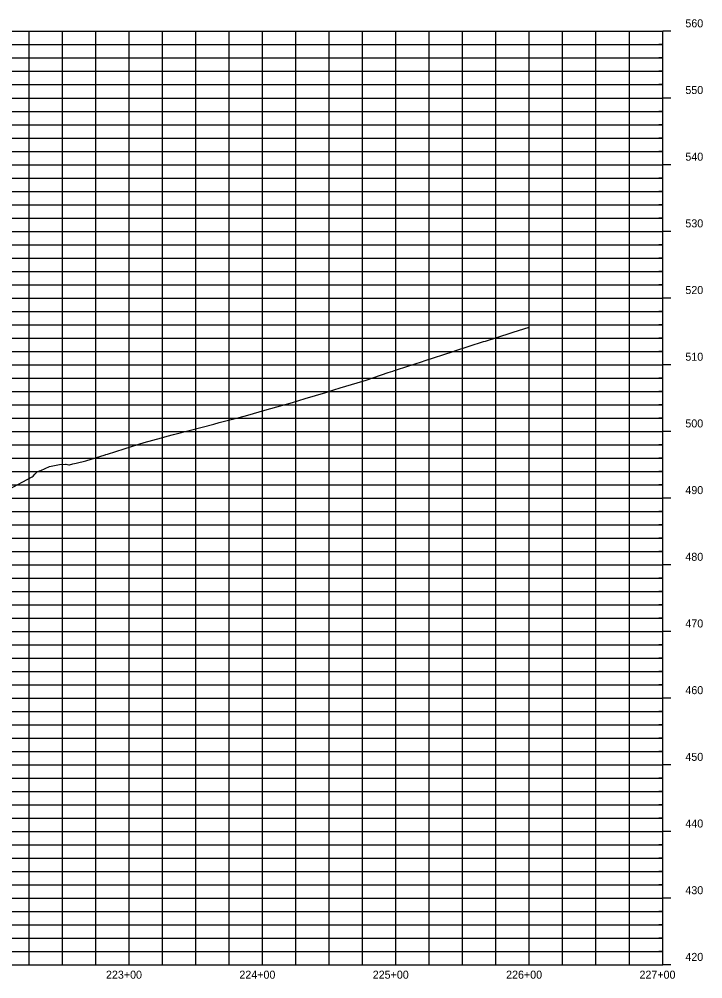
# Model space of a CAD drawing. Extents: x 1054002 to 1056762, y 395173 to 397393.
# Drawn here: x 1056250 to 1056762, y 395173 to 395893 of the extents above; entities that cross this region are included whole.
import ezdxf

# ---------------------------------------------------------------- set-up
doc = ezdxf.new("R2010")
doc.units = 0
for name, color, linetype in [('R_Axis_Annotation', 7, 'Continuous'), ('R_Exist Surface', 7, 'Continuous'), ('R_Grid', 7, 'Continuous'), ('R_Grid Annot', 7, 'Continuous'), ('R_Grid_Minor', 7, 'Continuous')]:
    doc.layers.add(name, color=color, linetype=linetype)

msp = doc.modelspace()

# ---------------------------------------------------------------- linework, layer by layer
at = {"layer": 'R_Exist Surface'}
msp.add_lwpolyline([(1056241.81, 395539.85), (1056259.67, 395549.45), (1056260.4, 395549.8), (1056261.45, 395551.26), (1056263.23, 395553.13), (1056263.71, 395553.34), (1056265.04, 395553.83), (1056265.14, 395553.88), (1056265.95, 395554.11), (1056272.48, 395557.17), (1056279.97, 395558.54), (1056284.63, 395558.84), (1056285.12, 395558.96), (1056287.08, 395558.26), (1056287.52, 395558.36), (1056289.96, 395559), (1056292.61, 395559.58), (1056299.79, 395561.45), (1056314.29, 395565.82), (1056314.9, 395565.99), (1056316.01, 395566.34), (1056334.83, 395572.32), (1056343.53, 395575.19), (1056356.5, 395578.61), (1056360.74, 395579.73), (1056365.53, 395581), (1056378.34, 395584.36), (1056395.66, 395588.9), (1056399.81, 395590.01), (1056414.66, 395593.91), (1056421.37, 395595.69), (1056433.9, 395599.33), (1056442.91, 395601.89), (1056454.64, 395605.21), (1056464.25, 395607.99), (1056479.62, 395612.64), (1056485.75, 395614.52), (1056490.43, 395615.97), (1056507.43, 395621.08), (1056509.94, 395621.93), (1056526.58, 395627.48), (1056529.85, 395628.56), (1056530.39, 395628.74), (1056533.56, 395629.78), (1056552.13, 395635.91), (1056553.4, 395636.32), (1056575.08, 395643.32), (1056576.52, 395643.79), (1056598.03, 395650.73), (1056599.47, 395651.17), (1056618.74, 395657.32), (1056620.18, 395657.76), (1056632.29, 395661.63)], dxfattribs=at)
at = {"layer": 'R_Grid'}
for p, q in [((1054032.29, 395883.41), (1056732.29, 395883.41)), ((1054032.29, 395883.41), (1056732.29, 395883.41)), ((1056332.29, 395183.41), (1056332.29, 395883.41)), ((1056432.29, 395183.41), (1056432.29, 395883.41)), ((1056532.29, 395183.41), (1056532.29, 395883.41)), ((1056632.29, 395183.41), (1056632.29, 395883.41)), ((1056732.29, 395183.41), (1056732.29, 395883.41)), ((1054032.29, 395833.41), (1056732.29, 395833.41)), ((1054032.29, 395783.41), (1056732.29, 395783.41)), ((1054032.29, 395733.41), (1056732.29, 395733.41)), ((1054032.29, 395683.41), (1056732.29, 395683.41)), ((1054032.29, 395633.41), (1056732.29, 395633.41)), ((1054032.29, 395583.41), (1056732.29, 395583.41)), ((1054032.29, 395533.41), (1056732.29, 395533.41)), ((1054032.29, 395483.41), (1056732.29, 395483.41)), ((1054032.29, 395433.41), (1056732.29, 395433.41)), ((1054032.29, 395383.41), (1056732.29, 395383.41)), ((1054032.29, 395333.41), (1056732.29, 395333.41)), ((1054032.29, 395283.41), (1056732.29, 395283.41)), ((1054032.29, 395233.41), (1056732.29, 395233.41)), ((1054032.29, 395183.41), (1056732.29, 395183.41))]:
    msp.add_line(p, q, dxfattribs=at)
at = {"layer": 'R_Grid Annot'}
for p, q in [((1056738.29, 395883.41), (1056732.29, 395883.41)), ((1056738.29, 395883.41), (1056732.29, 395883.41)), ((1056732.29, 395873.41), (1056729.29, 395873.41)), ((1056732.29, 395863.41), (1056729.29, 395863.41)), ((1056732.29, 395853.41), (1056729.29, 395853.41)), ((1056732.29, 395843.41), (1056729.29, 395843.41)), ((1056738.29, 395833.41), (1056732.29, 395833.41)), ((1056732.29, 395823.41), (1056729.29, 395823.41)), ((1056732.29, 395813.41), (1056729.29, 395813.41)), ((1056732.29, 395803.41), (1056729.29, 395803.41)), ((1056732.29, 395793.41), (1056729.29, 395793.41)), ((1056738.29, 395783.41), (1056732.29, 395783.41)), ((1056732.29, 395773.41), (1056729.29, 395773.41)), ((1056732.29, 395763.41), (1056729.29, 395763.41)), ((1056732.29, 395753.41), (1056729.29, 395753.41)), ((1056732.29, 395743.41), (1056729.29, 395743.41)), ((1056738.29, 395733.41), (1056732.29, 395733.41)), ((1056732.29, 395723.41), (1056729.29, 395723.41)), ((1056732.29, 395713.41), (1056729.29, 395713.41)), ((1056732.29, 395703.41), (1056729.29, 395703.41)), ((1056732.29, 395693.41), (1056729.29, 395693.41)), ((1056738.29, 395683.41), (1056732.29, 395683.41)), ((1056732.29, 395673.41), (1056729.29, 395673.41)), ((1056732.29, 395663.41), (1056729.29, 395663.41)), ((1056732.29, 395653.41), (1056729.29, 395653.41)), ((1056732.29, 395643.41), (1056729.29, 395643.41)), ((1056738.29, 395633.41), (1056732.29, 395633.41)), ((1056732.29, 395623.41), (1056729.29, 395623.41)), ((1056732.29, 395613.41), (1056729.29, 395613.41)), ((1056732.29, 395603.41), (1056729.29, 395603.41)), ((1056732.29, 395593.41), (1056729.29, 395593.41)), ((1056738.29, 395583.41), (1056732.29, 395583.41)), ((1056732.29, 395573.41), (1056729.29, 395573.41)), ((1056732.29, 395563.41), (1056729.29, 395563.41)), ((1056732.29, 395553.41), (1056729.29, 395553.41)), ((1056732.29, 395543.41), (1056729.29, 395543.41)), ((1056738.29, 395533.41), (1056732.29, 395533.41)), ((1056732.29, 395523.41), (1056729.29, 395523.41)), ((1056732.29, 395513.41), (1056729.29, 395513.41)), ((1056732.29, 395503.41), (1056729.29, 395503.41)), ((1056732.29, 395493.41), (1056729.29, 395493.41)), ((1056738.29, 395483.41), (1056732.29, 395483.41)), ((1056732.29, 395473.41), (1056729.29, 395473.41)), ((1056732.29, 395463.41), (1056729.29, 395463.41)), ((1056732.29, 395453.41), (1056729.29, 395453.41)), ((1056732.29, 395443.41), (1056729.29, 395443.41)), ((1056738.29, 395433.41), (1056732.29, 395433.41)), ((1056732.29, 395423.41), (1056729.29, 395423.41)), ((1056732.29, 395413.41), (1056729.29, 395413.41)), ((1056732.29, 395403.41), (1056729.29, 395403.41)), ((1056732.29, 395393.41), (1056729.29, 395393.41)), ((1056738.29, 395383.41), (1056732.29, 395383.41)), ((1056732.29, 395373.41), (1056729.29, 395373.41)), ((1056732.29, 395363.41), (1056729.29, 395363.41)), ((1056732.29, 395353.41), (1056729.29, 395353.41)), ((1056732.29, 395343.41), (1056729.29, 395343.41)), ((1056738.29, 395333.41), (1056732.29, 395333.41)), ((1056732.29, 395323.41), (1056729.29, 395323.41)), ((1056732.29, 395313.41), (1056729.29, 395313.41)), ((1056732.29, 395303.41), (1056729.29, 395303.41)), ((1056732.29, 395293.41), (1056729.29, 395293.41)), ((1056738.29, 395283.41), (1056732.29, 395283.41)), ((1056732.29, 395273.41), (1056729.29, 395273.41)), ((1056732.29, 395263.41), (1056729.29, 395263.41)), ((1056732.29, 395253.41), (1056729.29, 395253.41)), ((1056732.29, 395243.41), (1056729.29, 395243.41)), ((1056738.29, 395233.41), (1056732.29, 395233.41)), ((1056732.29, 395223.41), (1056729.29, 395223.41)), ((1056732.29, 395213.41), (1056729.29, 395213.41)), ((1056732.29, 395203.41), (1056729.29, 395203.41)), ((1056732.29, 395193.41), (1056729.29, 395193.41)), ((1056738.29, 395183.41), (1056732.29, 395183.41))]:
    msp.add_line(p, q, dxfattribs=at)
at = {"layer": 'R_Grid_Minor'}
for p, q in [((1056257.29, 395183.41), (1056257.29, 395883.41)), ((1056282.29, 395183.41), (1056282.29, 395883.41)), ((1056307.29, 395183.41), (1056307.29, 395883.41)), ((1056357.29, 395183.41), (1056357.29, 395883.41)), ((1056382.29, 395183.41), (1056382.29, 395883.41)), ((1056407.29, 395183.41), (1056407.29, 395883.41)), ((1056457.29, 395183.41), (1056457.29, 395883.41)), ((1056482.29, 395183.41), (1056482.29, 395883.41)), ((1056507.29, 395183.41), (1056507.29, 395883.41)), ((1056557.29, 395183.41), (1056557.29, 395883.41)), ((1056582.29, 395183.41), (1056582.29, 395883.41)), ((1056607.29, 395183.41), (1056607.29, 395883.41)), ((1056657.29, 395183.41), (1056657.29, 395883.41)), ((1056682.29, 395183.41), (1056682.29, 395883.41)), ((1056707.29, 395183.41), (1056707.29, 395883.41)), ((1054032.29, 395873.41), (1056732.29, 395873.41)), ((1054032.29, 395863.41), (1056732.29, 395863.41)), ((1054032.29, 395853.41), (1056732.29, 395853.41)), ((1054032.29, 395843.41), (1056732.29, 395843.41)), ((1054032.29, 395823.41), (1056732.29, 395823.41)), ((1054032.29, 395813.41), (1056732.29, 395813.41)), ((1054032.29, 395803.41), (1056732.29, 395803.41)), ((1054032.29, 395793.41), (1056732.29, 395793.41)), ((1054032.29, 395773.41), (1056732.29, 395773.41)), ((1054032.29, 395763.41), (1056732.29, 395763.41)), ((1054032.29, 395753.41), (1056732.29, 395753.41)), ((1054032.29, 395743.41), (1056732.29, 395743.41)), ((1054032.29, 395723.41), (1056732.29, 395723.41)), ((1054032.29, 395713.41), (1056732.29, 395713.41)), ((1054032.29, 395703.41), (1056732.29, 395703.41)), ((1054032.29, 395693.41), (1056732.29, 395693.41)), ((1054032.29, 395673.41), (1056732.29, 395673.41)), ((1054032.29, 395663.41), (1056732.29, 395663.41)), ((1054032.29, 395653.41), (1056732.29, 395653.41)), ((1054032.29, 395643.41), (1056732.29, 395643.41)), ((1054032.29, 395623.41), (1056732.29, 395623.41)), ((1054032.29, 395613.41), (1056732.29, 395613.41)), ((1054032.29, 395603.41), (1056732.29, 395603.41)), ((1054032.29, 395593.41), (1056732.29, 395593.41)), ((1054032.29, 395573.41), (1056732.29, 395573.41)), ((1054032.29, 395563.41), (1056732.29, 395563.41)), ((1054032.29, 395553.41), (1056732.29, 395553.41)), ((1054032.29, 395543.41), (1056732.29, 395543.41)), ((1054032.29, 395523.41), (1056732.29, 395523.41)), ((1054032.29, 395513.41), (1056732.29, 395513.41)), ((1054032.29, 395503.41), (1056732.29, 395503.41)), ((1054032.29, 395493.41), (1056732.29, 395493.41)), ((1054032.29, 395473.41), (1056732.29, 395473.41)), ((1054032.29, 395463.41), (1056732.29, 395463.41)), ((1054032.29, 395453.41), (1056732.29, 395453.41)), ((1054032.29, 395443.41), (1056732.29, 395443.41)), ((1054032.29, 395423.41), (1056732.29, 395423.41)), ((1054032.29, 395413.41), (1056732.29, 395413.41)), ((1054032.29, 395403.41), (1056732.29, 395403.41)), ((1054032.29, 395393.41), (1056732.29, 395393.41)), ((1054032.29, 395373.41), (1056732.29, 395373.41)), ((1054032.29, 395363.41), (1056732.29, 395363.41)), ((1054032.29, 395353.41), (1056732.29, 395353.41)), ((1054032.29, 395343.41), (1056732.29, 395343.41)), ((1054032.29, 395323.41), (1056732.29, 395323.41)), ((1054032.29, 395313.41), (1056732.29, 395313.41)), ((1054032.29, 395303.41), (1056732.29, 395303.41)), ((1054032.29, 395293.41), (1056732.29, 395293.41)), ((1054032.29, 395273.41), (1056732.29, 395273.41)), ((1054032.29, 395263.41), (1056732.29, 395263.41)), ((1054032.29, 395253.41), (1056732.29, 395253.41)), ((1054032.29, 395243.41), (1056732.29, 395243.41)), ((1054032.29, 395223.41), (1056732.29, 395223.41)), ((1054032.29, 395213.41), (1056732.29, 395213.41)), ((1054032.29, 395203.41), (1056732.29, 395203.41)), ((1054032.29, 395193.41), (1056732.29, 395193.41))]:
    msp.add_line(p, q, dxfattribs=at)

# ---------------------------------------------------------------- texts
at = {"layer": 'R_Axis_Annotation'}
for s, p in [('560', (1056749.3, 395886.41)), ('560', (1056749.3, 395886.41)), ('550', (1056749.3, 395836.41)), ('540', (1056749.3, 395786.41)), ('530', (1056749.3, 395736.41)), ('520', (1056749.3, 395686.41)), ('510', (1056749.3, 395636.41)), ('500', (1056749.3, 395586.41)), ('490', (1056749.3, 395536.41)), ('480', (1056749.3, 395486.41)), ('470', (1056749.3, 395436.41)), ('460', (1056749.3, 395386.41)), ('450', (1056749.3, 395336.41)), ('440', (1056749.3, 395286.41)), ('430', (1056749.3, 395236.41)), ('420', (1056749.3, 395186.41)), ('223+00', (1056314.89, 395173.06)), ('224+00', (1056414.89, 395173.06)), ('225+00', (1056514.89, 395173.06)), ('226+00', (1056614.89, 395173.06)), ('227+00', (1056714.89, 395173.06))]:
    msp.add_text(s, height=6, dxfattribs=at).set_placement(p)

doc.saveas('drawing.dxf')
